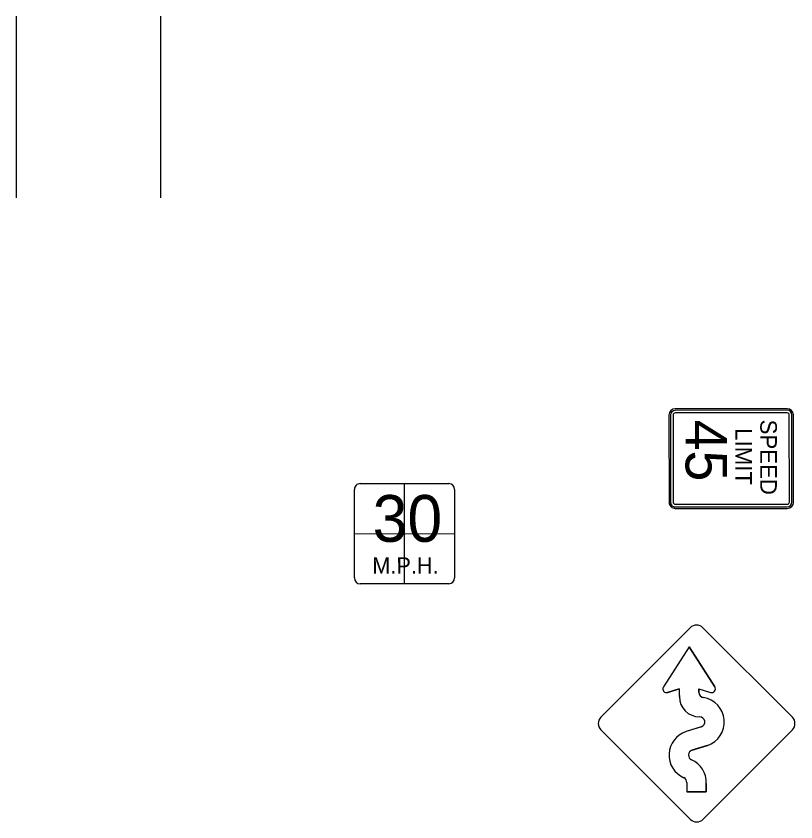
# Model space of a CAD drawing. Extents: x 1977705 to 1981198, y 827296 to 829291.
# Drawn here: x 1979348.8 to 1979794.1, y 828830.7 to 829290.7 of the extents above; entities that cross this region are included whole.
import ezdxf

# ---------------------------------------------------------------- set-up
doc = ezdxf.new("R2010")
doc.units = 0
doc.layers.add('Default', color=7, linetype='Continuous')
doc.layers.add('Level 34', color=7, linetype='Continuous')

msp = doc.modelspace()

# ---------------------------------------------------------------- linework, layer by layer
at = {"layer": 'Default'}
for p, q in [((1979789.18, 829066.54), (1979725.2, 829066.51)), ((1979789.18, 829065.65), (1979725.2, 829065.62)), ((1979789.18, 829064.17), (1979725.2, 829064.14)), ((1979721.64, 829062.95), (1979721.67, 829013.19)), ((1979722.53, 829062.95), (1979722.56, 829013.19)), ((1979724.01, 829062.95), (1979724.04, 829013.19)), ((1979790.39, 829013.22), (1979790.36, 829062.99)), ((1979791.87, 829013.22), (1979791.85, 829062.99)), ((1979792.76, 829013.22), (1979792.73, 829062.99)), ((1979599.21, 829020.49), (1979599.23, 828969.95)), ((1979725.22, 829012.01), (1979789.2, 829012.04)), ((1979725.22, 829010.52), (1979789.21, 829010.56)), ((1979725.22, 829009.64), (1979789.21, 829009.67)), ((1979682.77, 828890.44), (1979733.76, 828941.5)), ((1979792.1, 828890.53), (1979741.04, 828941.51)), ((1979733.11, 828930.65), (1979718.46, 828907.69)), ((1979733.11, 828930.65), (1979718.46, 828907.69)), ((1979733.11, 828930.65), (1979747.8, 828907.71)), ((1979747.8, 828907.71), (1979733.11, 828930.65)), ((1979727.55, 828906.61), (1979720.84, 828904.56)), ((1979720.93, 828904.59), (1979727.55, 828906.61)), ((1979727.55, 828906.61), (1979727.55, 828903.6)), ((1979727.55, 828906.61), (1979727.55, 828903.6)), ((1979727.55, 828903.6), (1979727.56, 828902.2)), ((1979727.56, 828902.2), (1979727.56, 828903.6)), ((1979738.71, 828906.62), (1979745.43, 828904.58)), ((1979738.71, 828906.62), (1979738.71, 828904.6)), ((1979738.71, 828904.6), (1979738.71, 828906.62)), ((1979738.71, 828906.62), (1979745.33, 828904.61)), ((1979740.07, 828884.92), (1979731.37, 828882.2)), ((1979740.16, 828884.95), (1979731.43, 828882.22)), ((1979733.84, 828832.17), (1979682.78, 828883.16)), ((1979741.13, 828832.18), (1979792.11, 828883.24)), ((1979743.49, 828874.29), (1979734.76, 828871.56)), ((1979734.83, 828871.58), (1979743.57, 828874.32)), ((1979731.79, 828853), (1979731.79, 828847.75)), ((1979731.79, 828852.97), (1979731.79, 828847.75)), ((1979742.96, 828847.76), (1979742.96, 828852.67)), ((1979742.96, 828852.66), (1979742.96, 828847.76)), ((1979742.96, 828847.76), (1979731.79, 828847.75)), ((1979731.79, 828847.75), (1979742.96, 828847.76))]:
    msp.add_line(p, q, dxfattribs=at)
for points in [[(1979545.32, 829023.8), (1979570.6, 829023.82)], [(1979570.6, 829023.82), (1979595.87, 829023.83)], [(1979542.01, 828969.92), (1979541.99, 829020.46)], [(1979570.63, 828966.59), (1979545.35, 828966.58)], [(1979595.9, 828966.61), (1979570.63, 828966.59)]]:
    msp.add_lwpolyline(points, dxfattribs=at)
for centre, radius, start, end in [((1979725.2, 829062.95), 3.55, 90.028, 180.028), ((1979725.2, 829062.95), 2.67, 90.028, 180.028), ((1979725.2, 829062.95), 1.18, 90.028, 180.028), ((1979789.18, 829062.98), 3.55, 0.028, 90.028), ((1979789.18, 829062.98), 2.67, 0.028, 90.028), ((1979789.18, 829062.98), 1.18, 0.028, 90.028), ((1979545.33, 829020.46), 3.34, 90.0178, 180.0308), ((1979595.87, 829020.49), 3.34, 0.0308, 90.0308), ((1979725.22, 829013.19), 3.55, 180.028, 270.028), ((1979725.22, 829013.19), 2.67, 180.028, 270.028), ((1979725.22, 829013.19), 1.18, 180.028, 270.028), ((1979789.2, 829013.22), 1.18, 270.028, 0.028), ((1979789.2, 829013.22), 3.55, 270.028, 0.028), ((1979789.2, 829013.22), 2.67, 270.028, 0.028), ((1979545.35, 828969.92), 3.34, 180.0308, 270.0308), ((1979595.9, 828969.95), 3.34, 270.0308, 0.0308)]:
    msp.add_arc(centre, radius, start, end, dxfattribs=at)
for centre, major_axis, start_param, end_param in [((1979737.4, 828937.86), (-5.15, 0), 3.927218, 5.498015), ((1979720.22, 828906.56), (-2.09, 0), 5.714639, 8.20034), ((1979720.22, 828906.56), (-2.09, 0), 5.714639, 8.20034), ((1979741.72, 828904.61), (3.01, 0), 3.14182, 4.598679), ((1979741.72, 828904.61), (3.01, 0), 3.14182, 4.578577), ((1979746.04, 828906.58), (-2.09, 0), 1.224893, 3.710594), ((1979746.04, 828906.58), (-2.09, 0), 1.224893, 3.710594), ((1979739.15, 828902.21), (11.58, 0.01), 3.14182, 4.712616), ((1979739.15, 828902.21), (11.58, 0.01), 3.14182, 4.712616), ((1979739.16, 828887.7), (-14.09, -0.01), 1.888919, 4.557647), ((1979739.16, 828887.7), (-14.09, -0.01), 1.888919, 4.557647), ((1979686.42, 828886.8), (-5.15, 0), 5.498015, 7.068811), ((1979739.16, 828887.7), (-2.93, 0), 1.88888, 4.712616), ((1979739.16, 828887.7), (-2.93, 0), 1.88888, 4.712616), ((1979788.46, 828886.88), (-5.15, 0), 2.356422, 3.927218), ((1979735.74, 828868.8), (14.09, 0.01), 1.885456, 4.296934), ((1979735.74, 828868.8), (14.09, 0.01), 1.885456, 4.296934), ((1979735.74, 828868.8), (2.93, 0), 1.885456, 4.296934), ((1979735.74, 828868.8), (2.93, 0), 1.885456, 4.296777), ((1979728.88, 828853.23), (-14.09, -0.01), 3.10118, 4.296967), ((1979728.88, 828853.23), (-14.09, -0.01), 3.10118, 4.296934), ((1979735.74, 828868.8), (2.93, 0), 4.296896, 4.296934), ((1979728.88, 828853.23), (-14.09, -0.01), 4.296942, 4.296967), ((1979728.88, 828853.23), (-2.93, 0), 3.064816, 4.296935), ((1979728.88, 828853.23), (-2.93, 0), 3.064816, 4.296934), ((1979737.48, 828835.82), (5.15, 0), 3.927218, 5.498015)]:
    msp.add_ellipse(centre, major_axis=major_axis, ratio=0.999999, start_param=start_param, end_param=end_param, dxfattribs=at)
at = {"layer": 'Level 34'}
for p, q in [((1979348.81, 829290.65), (1979348.87, 829186.93)), ((1979431.19, 829290.69), (1979431.25, 829186.97)), ((1979570.63, 828966.59), (1979570.6, 829023.82)), ((1979542, 828995.19), (1979599.22, 828995.22))]:
    msp.add_line(p, q, dxfattribs=at)

# ---------------------------------------------------------------- texts
at = {"layer": 'Default'}
for s, height, rotation, p in [('45', 23.697, 270.028, (1979731.12, 829060.32)), ('SPEED', 9.479, 270.028, (1979773.78, 829060.32)), ('LIMIT', 9.479, 270.028, (1979759.56, 829055.43)), ('30', 26.703, 0.0308, (1979552.42, 828990.55)), ('M.P.H.', 9.27, 0.0308, (1979552.21, 828972.39))]:
    msp.add_text(s, height=height, rotation=rotation, dxfattribs=at).set_placement(p)

doc.saveas('drawing.dxf')
